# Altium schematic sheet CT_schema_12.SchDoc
size 519 x 434 mm
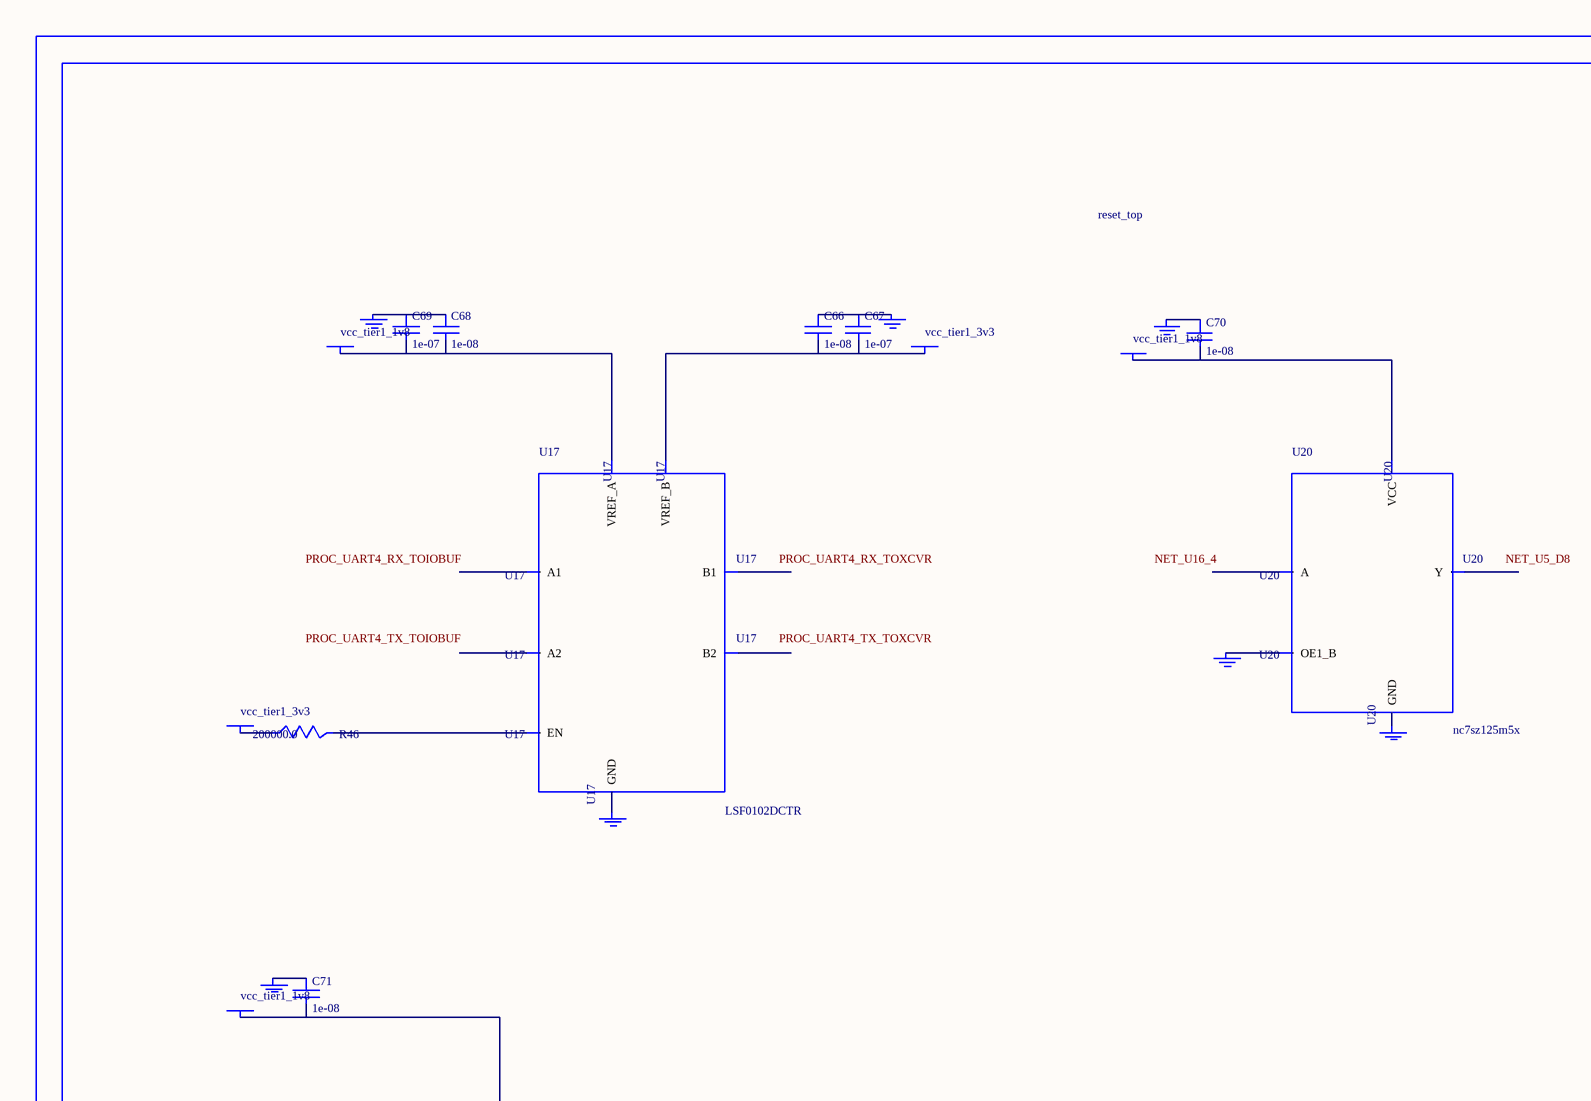
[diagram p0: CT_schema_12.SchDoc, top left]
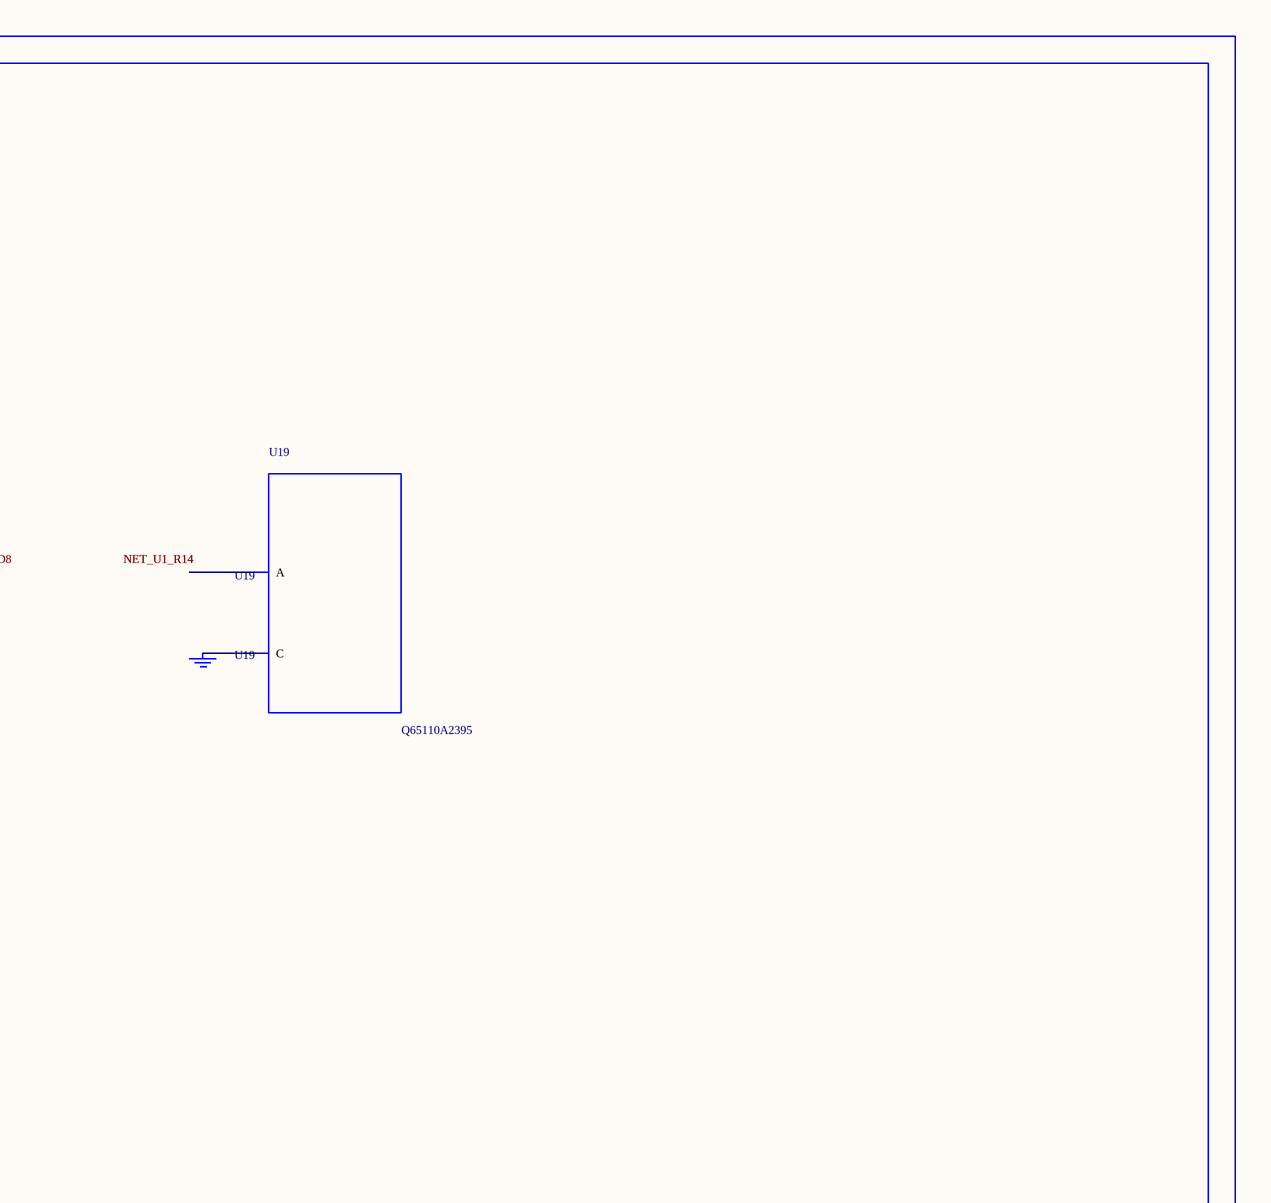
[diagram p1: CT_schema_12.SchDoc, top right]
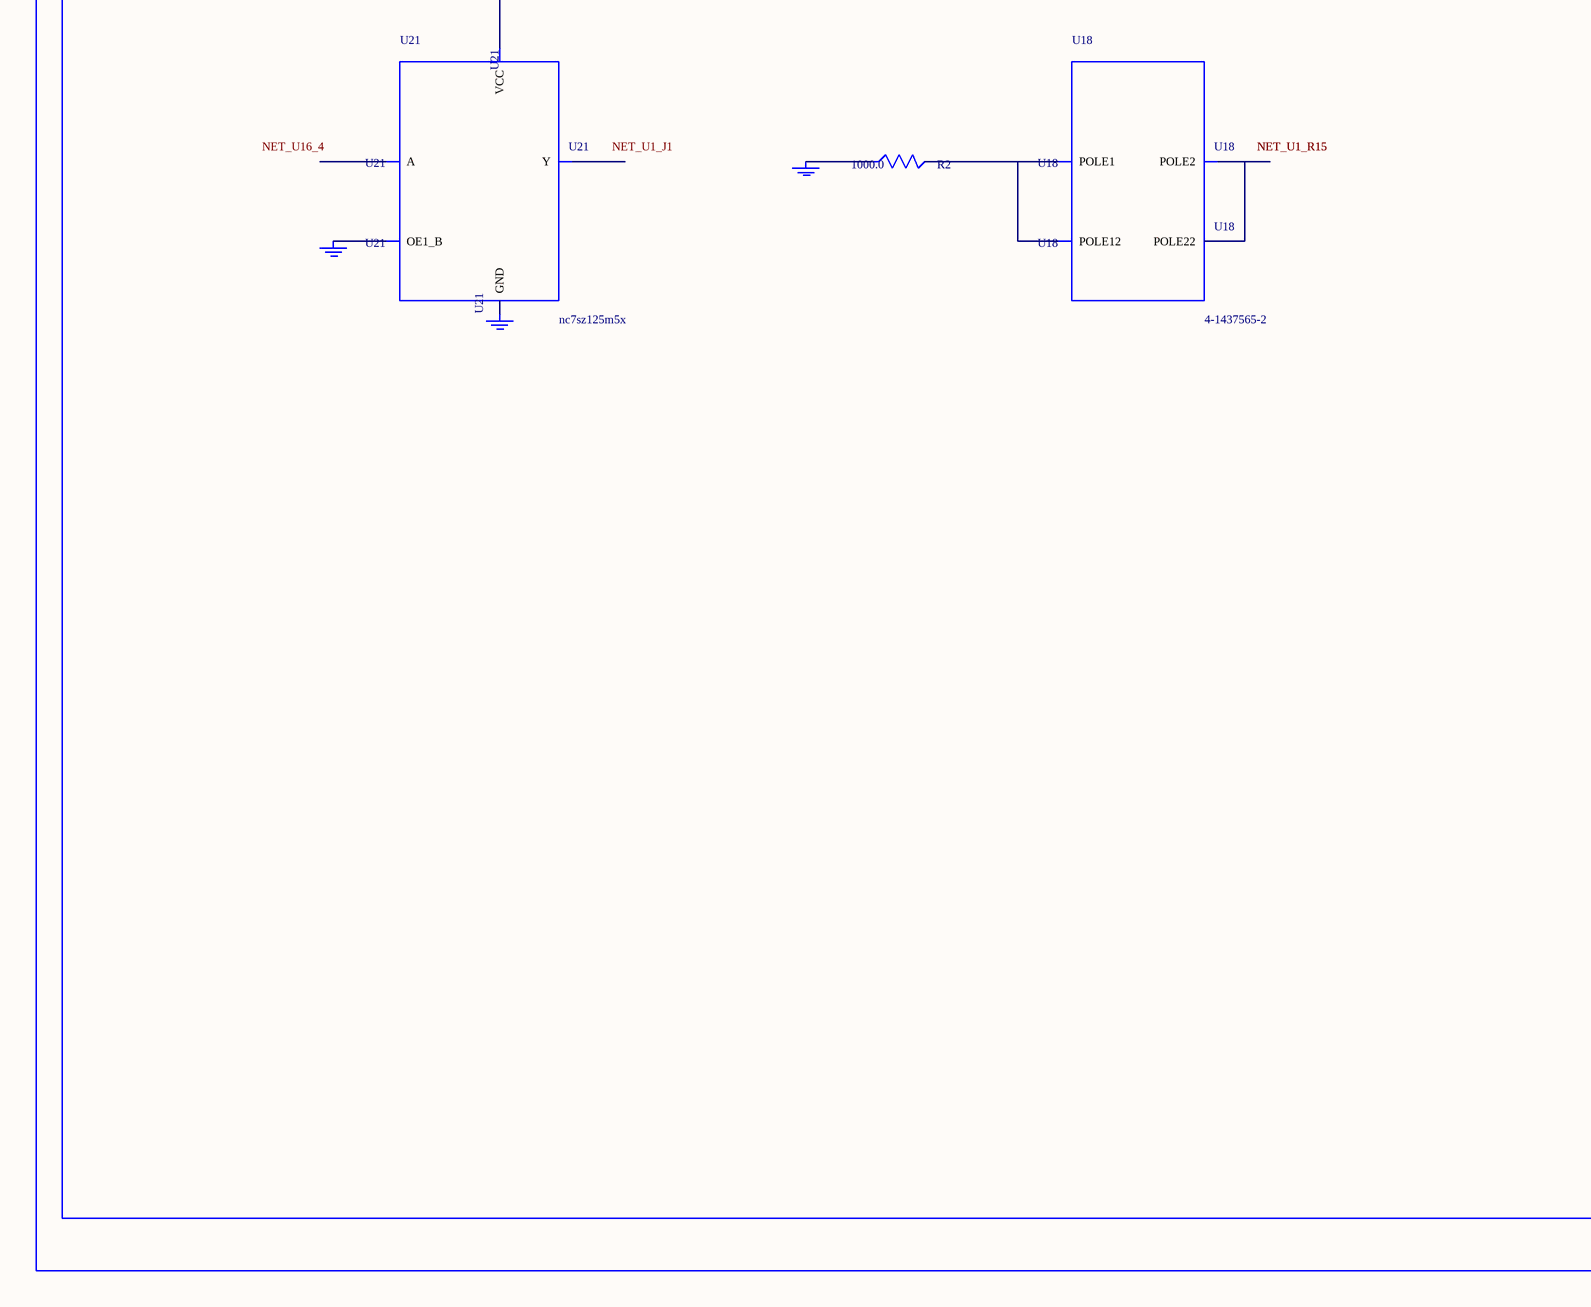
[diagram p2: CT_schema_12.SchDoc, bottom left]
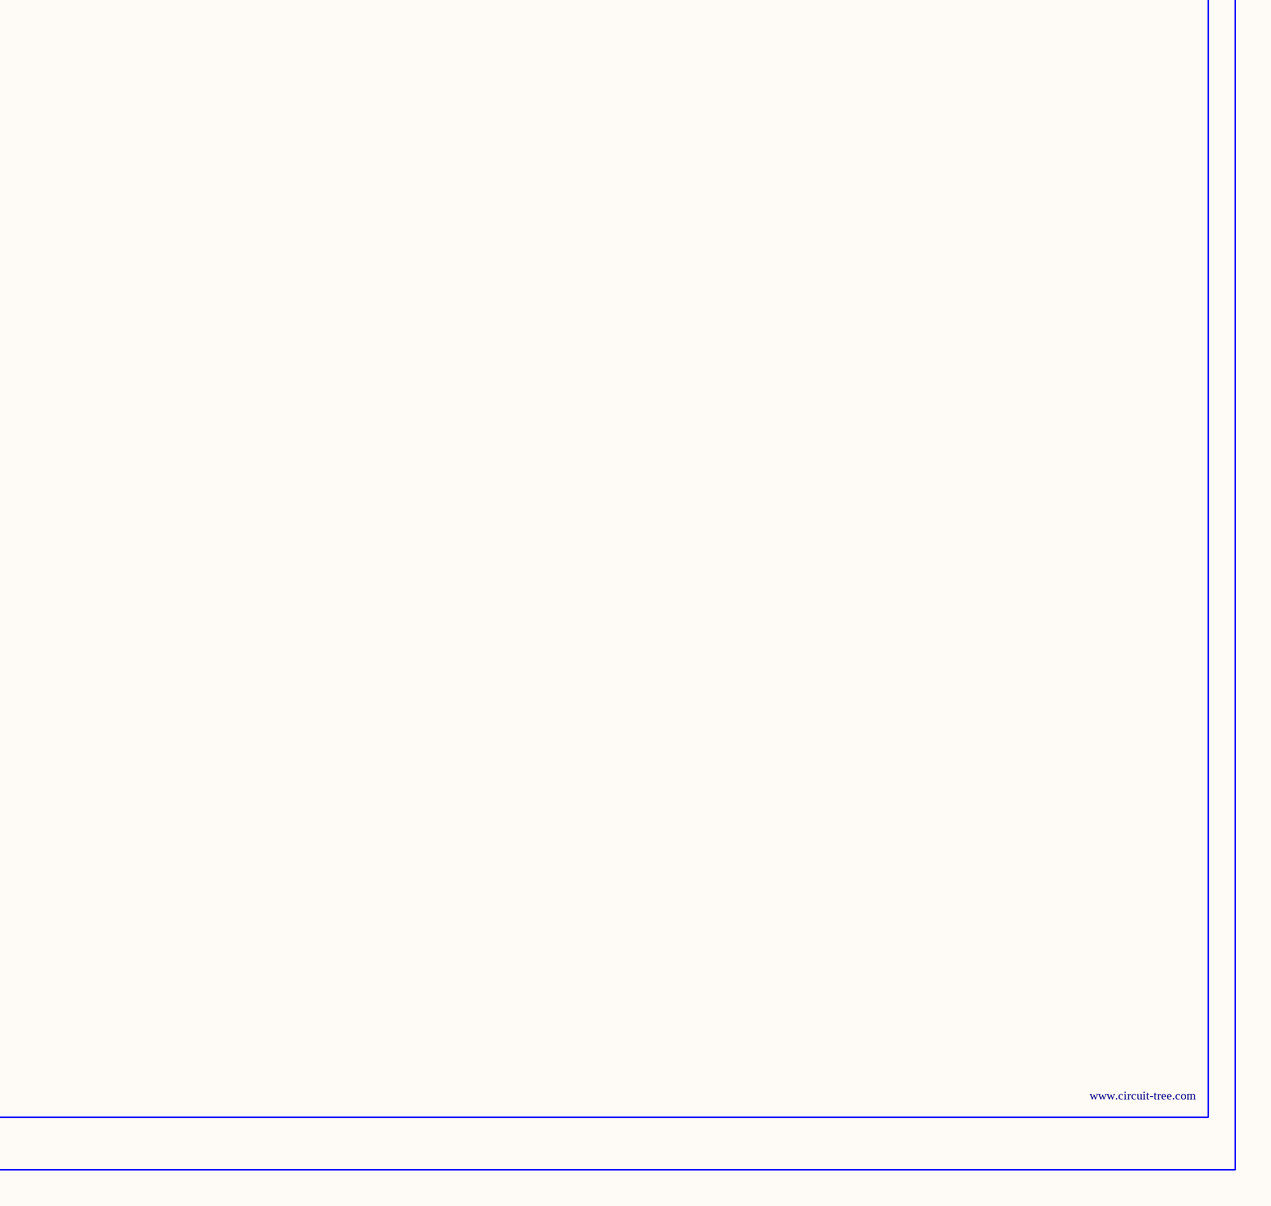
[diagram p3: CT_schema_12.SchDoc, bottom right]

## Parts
BORDER11  (no value)
C66  1e-08  [C0402]
C67  1e-07  [C0402]
C68  1e-08  [C0402]
C69  1e-07  [C0402]
C70  1e-08  [C0402]
C71  1e-08  [C0402]
GND_INSTANCE_11_0  (no value)
GND_INSTANCE_11_1  (no value)
GND_INSTANCE_11_2  (no value)
GND_INSTANCE_11_3  (no value)
GND_INSTANCE_11_4  (no value)
GND_INSTANCE_11_5  (no value)
GND_INSTANCE_11_6  (no value)
GND_INSTANCE_11_7  (no value)
GND_INSTANCE_11_8  (no value)
GND_INSTANCE_11_9  (no value)
GND_INSTANCE_11_10  (no value)
POWER_INSTANCE_11_0  vcc_tier1_1v8
POWER_INSTANCE_11_1  vcc_tier1_3v3
POWER_INSTANCE_11_2  vcc_tier1_3v3
POWER_INSTANCE_11_3  vcc_tier1_1v8
POWER_INSTANCE_11_4  vcc_tier1_1v8
R2  1000.0  [R0603]
R46  200000.0  [R0603]
U17  LSF0102DCTR  [DCU0008A_N]
U18  4-1437565-2  [SW_4-1437565-2]
U19  Q65110A2395  [LGM67K-G1J2-24-Z]
U20  nc7sz125m5x  [NC7SZ125M5X]
U21  nc7sz125m5x  [NC7SZ125M5X]

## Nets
NetC66_1: C66.1 C67.1 GND_INSTANCE_11_1.0(GND)
NetC66_2: C66.2 C67.2 POWER_INSTANCE_11_1.0(PWR) U17.7(VREF_B)
NetC68_1: C68.1 C69.1 GND_INSTANCE_11_0.0(GND)
NetC68_2: C68.2 C69.2 POWER_INSTANCE_11_0.0(PWR) U17.2(VREF_A)
NetC70_1: C70.1 GND_INSTANCE_11_5.0(GND)
NetC70_2: C70.2 POWER_INSTANCE_11_3.0(PWR) U20.5(VCC)
NetC71_1: C71.1 GND_INSTANCE_11_8.0(GND)
NetC71_2: C71.2 POWER_INSTANCE_11_4.0(PWR) U21.5(VCC)
NetGND_INSTANCE_11_2_0: GND_INSTANCE_11_2.0(GND) U17.1(GND)
NetGND_INSTANCE_11_3_0: GND_INSTANCE_11_3.0(GND) R2.1
NetGND_INSTANCE_11_4_0: GND_INSTANCE_11_4.0(GND) U19.C
NetGND_INSTANCE_11_6_0: GND_INSTANCE_11_6.0(GND) U20.1(OE1_B)
NetGND_INSTANCE_11_7_0: GND_INSTANCE_11_7.0(GND) U20.3(GND)
NetGND_INSTANCE_11_9_0: GND_INSTANCE_11_9.0(GND) U21.1(OE1_B)
NetGND_INSTANCE_11_10_0: GND_INSTANCE_11_10.0(GND) U21.3(GND)
NetPOWER_INSTANCE_11_2_0: POWER_INSTANCE_11_2.0(PWR) R46.1
NetR2_2: R2.2 U18.1(POLE1) U18.2(POLE12)
NetR46_2: R46.2 U17.8(EN)
NetU18_3: U18.3(POLE2) U18.4(POLE22)

Not connected (* = marked no-connect by the designer): U17 3(A1) 4(A2) 5(B2) 6(B1); U19 A; U20 2(A) 4(Y); U21 2(A) 4(Y)

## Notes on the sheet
- Labels drawn without touching a wire or pin: NET_U1_J1, NET_U5_D8, NET_U16_4, PROC_UART4_RX_TOIOBUF, PROC_UART4_RX_TOXCVR, PROC_UART4_TX_TOIOBUF, PROC_UART4_TX_TOXCVR

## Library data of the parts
BORDER11 = BORDER_PAGE11
C66 C68 C70 C71 = C0402C103K3RAC
C67 C69 = C0402C104K3RACTU
GND_INSTANCE_11_0-GND_INSTANCE_11_10 = GND
POWER_INSTANCE_11_0-POWER_INSTANCE_11_4 = PWR
R2 = RC0603JR-071KL
R46 = RC0603JR-07200KL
